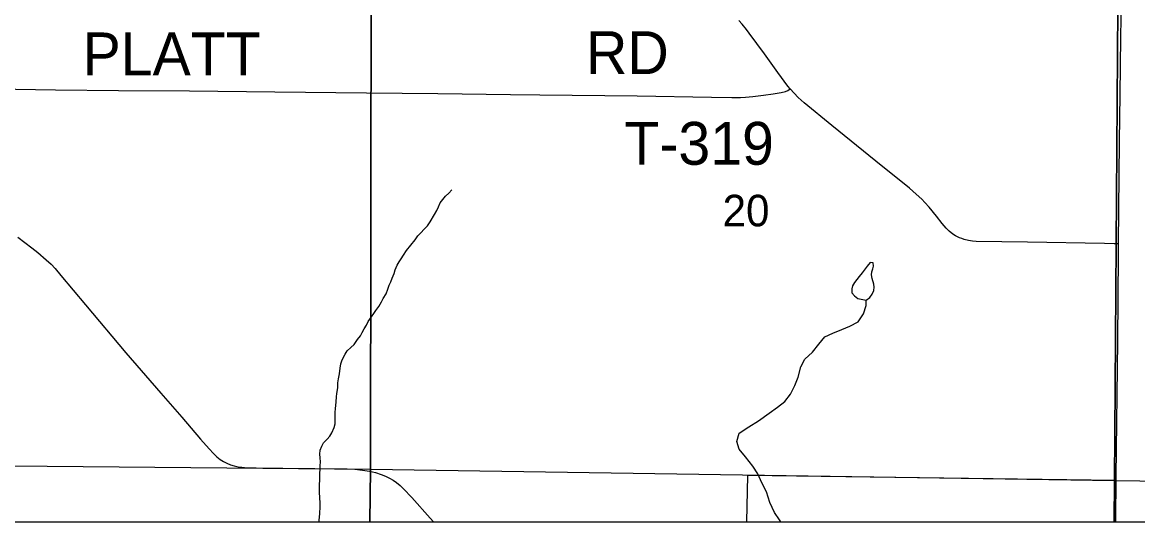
# Model space of a CAD drawing. Extents: x 0 to 34, y 0 to 22.
# Drawn here: x 3.988 to 5.468, y 14.1 to 14.762 of the extents above; entities that cross this region are included whole.
import ezdxf

# ---------------------------------------------------------------- set-up
doc = ezdxf.new("R2010")
doc.units = 0
for name, color, linetype in [('GM_X_Corporation', 7, 'Continuous'), ('GM_X_County_Road', 7, 'Continuous'), ('GM_X_Minor_Lake', 7, 'Continuous'), ('GM_X_Minor_River', 7, 'Continuous'), ('GM_X_Section_Text', 7, 'Continuous'), ('GM_X_State_Route', 7, 'Continuous'), ('GM_X_Township_Road', 7, 'Continuous'), ('GM_X_Township_Road_Text', 7, 'Continuous'), ('SH_Data', 7, 'Continuous')]:
    doc.layers.add(name, color=color, linetype=linetype)

msp = doc.modelspace()

# ---------------------------------------------------------------- linework, layer by layer
at = {"layer": 'GM_X_Corporation'}
msp.add_lwpolyline([(3.4754, 17.1134), (3.4672, 16.2781), (3.4601, 16.0804), (3.4533, 15.0461), (3.4516, 14.7743), (3.448, 14.3179), (3.4463, 14.1), (8.9, 14.1)], dxfattribs=at)
for points in [[(3.4532, 15.1884), (4.4514, 15.172), (4.4501, 14.1693), (3.4483, 14.1786), (3.4477, 14.2699)], [(4.4514, 15.172), (5.4447, 15.1591), (5.4377, 14.1543), (4.4501, 14.1693)], [(5.4447, 15.1591), (6.4527, 15.1394), (6.4438, 14.1407), (5.4377, 14.1543)], [(3.4477, 14.1), (4.4491, 14.1), (4.4501, 14.1693), (3.4483, 14.1786)], [(4.4491, 14.1), (5.4372, 14.1), (5.4377, 14.1543), (4.4501, 14.1693)], [(4.9491, 14.1), (5.4391, 14.1), (5.4392, 14.1061), (5.4395, 14.1544), (4.9503, 14.1613)], [(5.4372, 14.1), (6.4436, 14.1), (6.4438, 14.1407), (5.4377, 14.1543)]]:
    msp.add_lwpolyline(points, close=True, dxfattribs=at)
at = {"layer": 'GM_X_County_Road'}
for points in [[(5.4432, 14.4685), (5.4374, 14.4686), (5.4243, 14.469), (5.3224, 14.4707), (5.2541, 14.4718), (5.2492, 14.4721), (5.2437, 14.4728), (5.2382, 14.4742), (5.2349, 14.4754), (5.2321, 14.4764), (5.2291, 14.4776), (5.2266, 14.4789), (5.2229, 14.4813), (5.2184, 14.4851), (5.2143, 14.4895), (5.2089, 14.4955), (5.2012, 14.5051), (5.1915, 14.5172), (5.1861, 14.5233), (5.1818, 14.5278), (5.1745, 14.5346), (5.1655, 14.5423), (5.1208, 14.5782), (5.0625, 14.6254), (5.0255, 14.6557), (5.0176, 14.6627), (5.0072, 14.6739), (5.0041, 14.6778), (4.9907, 14.6957), (4.9732, 14.7206), (4.9528, 14.748), (4.949, 14.753), (4.9434, 14.7597), (4.9388, 14.7648)], [(3.9816, 14.4772), (4.0005, 14.4631), (4.0083, 14.457), (4.0196, 14.4474), (4.0259, 14.4415), (4.0314, 14.4356), (4.0391, 14.4267), (4.0716, 14.3875), (4.1253, 14.3239), (4.1717, 14.2704), (4.1994, 14.2385), (4.2245, 14.2093), (4.2356, 14.1966), (4.2415, 14.1902), (4.2461, 14.1859), (4.2506, 14.1824), (4.2548, 14.1797), (4.2593, 14.1774), (4.264, 14.1755), (4.2688, 14.174), (4.2744, 14.1728), (4.2794, 14.1721), (4.2868, 14.1715), (4.2981, 14.1712), (4.3335, 14.1709), (4.4189, 14.1701), (4.4294, 14.1695), (4.4395, 14.1685), (4.4485, 14.1671), (4.4567, 14.165), (4.4641, 14.1627), (4.4698, 14.1604), (4.4754, 14.1577), (4.4801, 14.155), (4.4846, 14.1518), (4.4893, 14.1478), (4.4937, 14.1435), (4.5048, 14.132), (4.5294, 14.1047), (4.5336, 14.1)]]:
    msp.add_lwpolyline(points, dxfattribs=at)
at = {"layer": 'GM_X_Minor_Lake'}
msp.add_line((5.097, 14.3962), (5.1079, 14.394), dxfattribs=at)
msp.add_lwpolyline([(5.1079, 14.394), (5.113, 14.3973), (5.1161, 14.4018), (5.1182, 14.4066), (5.1187, 14.4112), (5.118, 14.415), (5.116, 14.4227), (5.1153, 14.4276), (5.1154, 14.4314), (5.1167, 14.4352), (5.1176, 14.439), (5.1173, 14.4435), (5.1131, 14.4436), (5.1092, 14.4388), (5.1029, 14.4299), (5.0989, 14.425), (5.0958, 14.4213), (5.0923, 14.4172), (5.0899, 14.4128), (5.089, 14.409), (5.0892, 14.4037), (5.0925, 14.3994), (5.097, 14.3962)], dxfattribs=at)
at = {"layer": 'GM_X_Minor_River'}
for points in [[(4.403, 14.2299), (4.4033, 14.2398), (4.4031, 14.2447), (4.4037, 14.25), (4.4038, 14.2542), (4.4044, 14.2591), (4.405, 14.2656), (4.4055, 14.2701), (4.4065, 14.2773), (4.4068, 14.2842), (4.4077, 14.2895), (4.4087, 14.2959), (4.4097, 14.3035), (4.4107, 14.3092), (4.412, 14.3133), (4.4136, 14.3174), (4.4164, 14.3223), (4.4192, 14.3264), (4.4239, 14.3312), (4.4285, 14.3349), (4.4329, 14.3416), (4.4365, 14.3465), (4.4389, 14.3509), (4.4417, 14.3558), (4.4449, 14.3607), (4.4469, 14.3655), (4.4513, 14.3715), (4.4544, 14.376), (4.4572, 14.3801), (4.4611, 14.3853), (4.4644, 14.3917), (4.4668, 14.3962), (4.4708, 14.4021), (4.4729, 14.4082), (4.4749, 14.4138), (4.477, 14.4179), (4.4786, 14.4228), (4.4815, 14.4292), (4.4828, 14.4341), (4.4853, 14.4401), (4.4881, 14.4446), (4.4905, 14.4487), (4.4937, 14.4536), (4.4976, 14.4595), (4.5094, 14.474), (4.513, 14.4789), (4.5169, 14.4833), (4.5212, 14.4881), (4.5255, 14.4926), (4.5294, 14.4978), (4.535, 14.5075), (4.5379, 14.5128), (4.5403, 14.5176), (4.5427, 14.5229), (4.5459, 14.5274), (4.5494, 14.5318), (4.5541, 14.5359), (4.558, 14.5403)], [(4.9947, 14.1), (4.9928, 14.1025), (4.9862, 14.1122), (4.9802, 14.1253), (4.9756, 14.1394), (4.9695, 14.1514), (4.9641, 14.1633), (4.9576, 14.1734), (4.9477, 14.1858), (4.9393, 14.1963), (4.9365, 14.2063), (4.9395, 14.2172), (4.9522, 14.2256), (4.965, 14.2336), (4.9793, 14.2438), (4.9905, 14.2518), (5.0002, 14.2595), (5.0077, 14.2692), (5.0133, 14.2804), (5.0178, 14.2917), (5.0212, 14.3053), (5.0264, 14.3154), (5.0366, 14.325), (5.0452, 14.3354), (5.0531, 14.345), (5.0638, 14.35), (5.0757, 14.3547), (5.0865, 14.3593), (5.0976, 14.365), (5.1044, 14.3755), (5.1081, 14.3868), (5.1079, 14.394)], [(4.3818, 14.1), (4.3819, 14.1019), (4.3824, 14.1061), (4.3829, 14.111), (4.3832, 14.1198), (4.3831, 14.1259), (4.3829, 14.1308), (4.3825, 14.14), (4.3823, 14.1449), (4.3833, 14.1742), (4.3835, 14.1795), (4.3833, 14.1848), (4.3827, 14.1894), (4.3833, 14.1947), (4.3854, 14.2), (4.3878, 14.2045), (4.3925, 14.2093), (4.396, 14.2134), (4.3988, 14.2178), (4.4017, 14.225), (4.403, 14.2299)]]:
    msp.add_lwpolyline(points, dxfattribs=at)
at = {"layer": 'GM_X_State_Route'}
msp.add_line((5.4398, 14.154), (5.4398, 14.1599), dxfattribs=at)
for points in [[(5.4398, 14.1599), (5.4419, 14.3392), (5.4431, 14.4541), (5.4432, 14.4685), (5.4445, 14.6044), (5.4451, 14.6665), (5.4461, 14.7423), (5.4468, 14.7938), (5.4477, 14.8534), (5.4481, 14.8602), (5.4488, 14.8662), (5.45, 14.8721), (5.4519, 14.8781), (5.4544, 14.8841), (5.4571, 14.8895), (5.4619, 14.8983), (5.4719, 14.9162)], [(5.4393, 14.1), (5.4394, 14.1056), (5.4398, 14.154)]]:
    msp.add_lwpolyline(points, dxfattribs=at)
at = {"layer": 'GM_X_Township_Road'}
msp.add_lwpolyline([(3.9523, 14.674), (4.0319, 14.6729), (4.1156, 14.672), (4.2098, 14.6714), (4.3229, 14.6699), (4.4447, 14.6689), (4.5394, 14.6678), (4.6359, 14.6664), (4.6749, 14.6663), (4.8041, 14.6646), (4.9029, 14.6632), (4.9297, 14.6625), (4.9414, 14.6628), (4.9476, 14.6631), (4.9575, 14.664), (4.9717, 14.6658), (4.9846, 14.6675), (4.995, 14.6692), (5.001, 14.6706), (5.0039, 14.6718), (5.0072, 14.6739)], dxfattribs=at)
at = {"layer": 'SH_Data'}
msp.add_line((2.1, 14.1), (8.9, 14.1), dxfattribs=at)
msp.add_line((2.1, 14.1), (8.9, 14.1), dxfattribs=at)
msp.add_line((2.1, 14.1), (8.9, 14.1), dxfattribs=at)

# ---------------------------------------------------------------- texts
at = {"layer": 'GM_X_Section_Text'}
msp.add_text('20', height=0.04186, rotation=0, dxfattribs=at).set_placement((4.9174, 14.4917))
at = {"layer": 'GM_X_Township_Road_Text'}
for s, p in [('PLATT', (4.0678, 14.692)), ('RD', (4.7362, 14.6937)), ('T-319', (4.787, 14.5734))]:
    msp.add_text(s, height=0.05682, rotation=0, dxfattribs=at).set_placement(p)

doc.saveas('drawing.dxf')
